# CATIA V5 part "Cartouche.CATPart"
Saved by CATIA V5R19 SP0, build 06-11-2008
Part number: Cartouche
Publications: "L", "H", "P"
Bounding box of the stored display mesh (mm): x -50 to 0, y 0 to 80, z 0 to 80
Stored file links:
  G:\EU_thinkMotion\CFAO_2010\MMS_groupe3\MMS_groupe3\A reprendre\evulliez\evulliez\Cartouche.CATPart
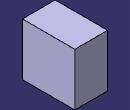
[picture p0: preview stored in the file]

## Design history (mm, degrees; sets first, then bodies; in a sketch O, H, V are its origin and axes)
Parameters
  L = 80 mm
  H = 80 mm
  P = 50 mm
Body1 (main body)
  Sketch1 on yz-plane, origin (0, 0, 0), H (0, 1, 0), V (0, 0, 1)
    line L1 (0, 0) -> (80, 0)
    line L2 (80, 0) -> (80, 80)
    line L3 (80, 80) -> (0, 80)
    line L4 (0, 80) -> (0, 0)
    length L3 = 80 {= L}
    length L2 = 80 {= H}
    horizontal: L1 H, L3 H
    vertical: L2 V, L4 V
  Pad1: profile Sketch1, direction (-1, 0, 0), length 50 {= P}
  Point1: type OnPlane, Support start face of Pad1, H 40 {= L /2}, V 40 {= H /2}, Direction (0, 1, 0)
